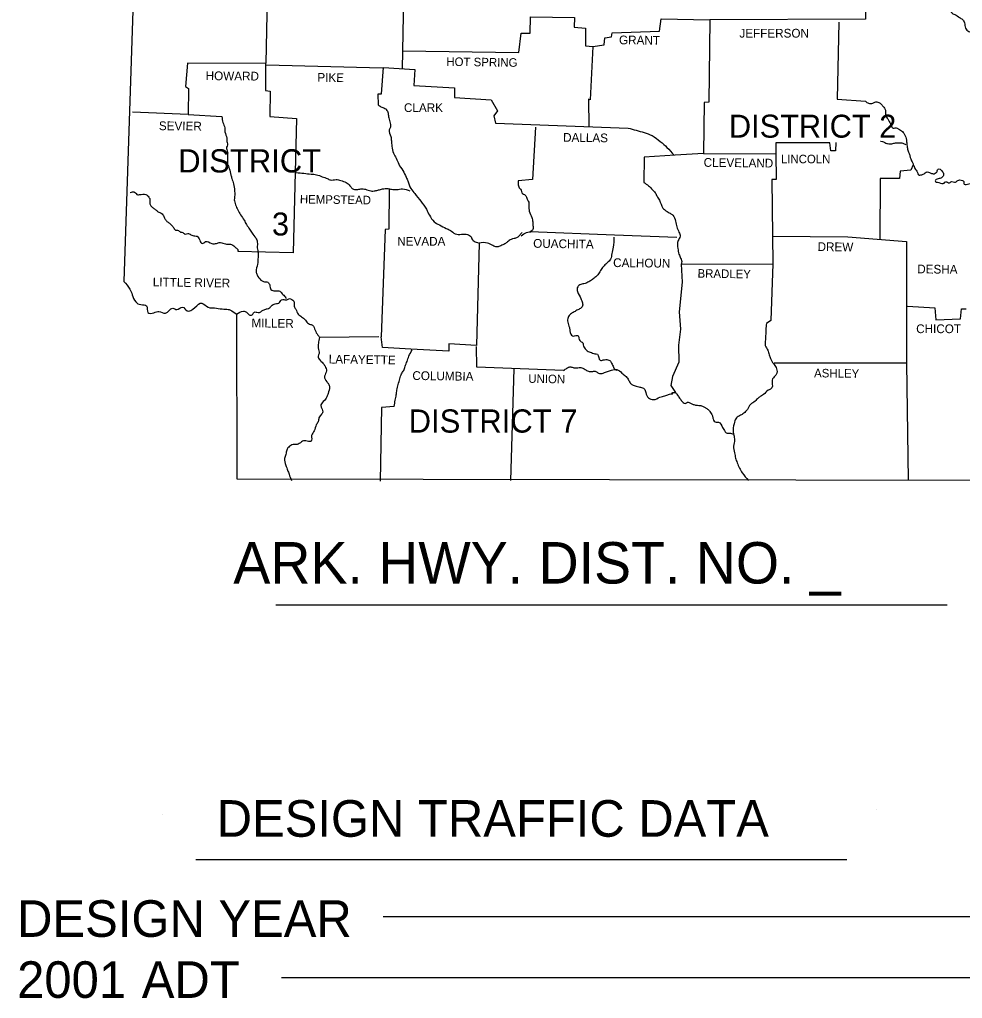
# Model space of a CAD drawing. Extents: x 76 to 6945, y -3933 to 2152.
# Drawn here: x 4972.5 to 5436, y -2483.3 to -2002.1 of the extents above; entities that cross this region are included whole.
import ezdxf

# ---------------------------------------------------------------- set-up
doc = ezdxf.new("R2010")
doc.units = 0
doc.layers.add('R_Draft', color=7, linetype='Continuous')

msp = doc.modelspace()

# ---------------------------------------------------------------- linework, layer by layer
at = {"layer": 'R_Draft'}
for p, q in [((5161.79, -1963.41), (5160.63, -2026.21)), ((5098.49, -2289.78), (5428.55, -2289.78)), ((5393.61, -2390.6), (5393.61, -2390.6)), ((5042.81, -2392.7), (5042.81, -2392.7)), ((5059.21, -2414.9), (5379.21, -2414.9)), ((5151.31, -2443.02), (5469.42, -2443.02)), ((5101.31, -2473.02), (5466.56, -2473.02))]:
    msp.add_line(p, q, dxfattribs=at)
for points in [[(5012.09, -1693.31), (5032.79, -1859.51), (5023.79, -2130.81)], [(5094.58, -1975.18), (5093.5, -2023.41)], [(5426.39, -1990.51), (5388.59, -1989.51), (5388.39, -2001.81), (5311.89, -2002.11)], [(5160.79, -2017.41), (5217.99, -2018.21), (5219.09, -2008.71), (5223.59, -2008.71), (5223.69, -2000.71), (5245.29, -2001.01), (5245.09, -2005.81), (5250.69, -2006.21), (5250.69, -2015.01), (5254.29, -2015.31), (5254.25, -2016.22)], [(5254.29, -2015.31), (5259.89, -2014.51), (5260.29, -2011.11), (5263.59, -2010.51), (5263.79, -2008.51), (5287.09, -2007.81), (5287.99, -2001.71), (5311.89, -2002.11)], [(5311.89, -2002.11), (5311.29, -2042.71), (5308.99, -2042.81), (5308.69, -2067.91)], [(5375.29, -2003.41), (5374.49, -2041.11), (5388.39, -2042.21)], [(5254.29, -2015.31), (5253.09, -2041.51), (5252.19, -2041.21), (5252.29, -2054.81)], [(5093.39, -2023.61), (5054.99, -2023.51), (5054.09, -2034.91), (5055.49, -2035.91), (5055.39, -2048.71), (5028.09, -2047.51)], [(5093.49, -2023.61), (5093.49, -2036.91), (5095.69, -2037.31), (5095.49, -2049.71), (5108.69, -2050.71), (5107.09, -2116.81), (5079.89, -2116.11)], [(5093.69, -2024.31), (5150.89, -2025.81)], [(5148.99, -2044.11), (5148.79, -2038.61), (5150.39, -2038.51), (5151.39, -2025.61), (5166.79, -2026.61), (5166.39, -2034.51), (5186.29, -2035.61), (5186.39, -2040.41), (5204.39, -2041.51), (5207.49, -2046.91), (5205.59, -2049.31), (5206.49, -2053.01), (5271.69, -2055.41)], [(5055.39, -2048.71), (5071.99, -2049.71)], [(5226.09, -2054.91), (5224.59, -2080.61), (5217.69, -2081.41)], [(5373.76, -2062.44), (5373.59, -2066.51), (5371.29, -2066.51), (5370.89, -2062.61), (5344.29, -2062.61), (5344.32, -2068.11)], [(5294.86, -2068.76), (5279.49, -2069.71), (5279.39, -2082.21)], [(5308.69, -2067.91), (5294.86, -2068.76)], [(5308.69, -2067.91), (5344.09, -2068.11)], [(5344.32, -2068.11), (5344.39, -2080.61), (5342.29, -2080.71), (5342.89, -2122.21)], [(5411.89, -2073.41), (5410.69, -2076.11), (5405.39, -2076.61), (5405.09, -2080.21), (5395.59, -2080.21), (5395.49, -2110.11)], [(5154.29, -2085.21), (5154.09, -2105.11), (5152.29, -2105.31), (5150.29, -2158.01)], [(5223.59, -2106.31), (5264.99, -2107.81), (5295.69, -2109.01)], [(5198.39, -2111.91), (5197.09, -2162.31), (5183.59, -2161.41), (5183.49, -2165.11), (5164.82, -2164.01)], [(5342.59, -2108.61), (5379.69, -2108.91), (5408.49, -2111.11)], [(5408.49, -2111.11), (5408.49, -2170.91), (5409.29, -2228.41)], [(5297.69, -2122.31), (5298.26, -2131.21), (5296.79, -2145.69), (5297.42, -2154.29), (5296.37, -2162.06), (5296.58, -2170.45), (5293.44, -2177.59), (5292.6, -2181.99), (5294.9, -2185.35)], [(5297.69, -2122.31), (5342.89, -2122.21)], [(5342.89, -2122.21), (5341.89, -2150.01), (5339.69, -2151.41)], [(5408.99, -2143.01), (5422.39, -2143.81), (5422.99, -2149.61), (5435.09, -2149.21), (5435.59, -2144.31), (5437.89, -2144.31)], [(5079.09, -2146.91), (5079.29, -2227.81), (5445.79, -2228.41)], [(5149.18, -2158.02), (5119.99, -2158.31)], [(5164.82, -2164.01), (5150.99, -2163.21), (5150.29, -2158.01)], [(5239.99, -2174.51), (5197.29, -2172.91), (5197.09, -2162.81)], [(5215.49, -2173.81), (5213.89, -2228.71)], [(5343.49, -2170.81), (5408.49, -2170.81)], [(5156.69, -2192.31), (5150.49, -2192.71), (5149.79, -2229.01)]]:
    msp.add_lwpolyline(points, dxfattribs=at)
for points in [[(5426.39, -1990.51), (5426.69, -1994.61), (5429.09, -1995.21), (5430.09, -1996.31), (5430.59, -1998.61), (5432.29, -1999.61), (5434.59, -2001.01), (5435.99, -2002.01), (5436.99, -2003.61), (5437.59, -2006.21), (5439.19, -2007.91), (5441.39, -2008.71), (5442.99, -2010.61), (5443.99, -2013.31), (5445.59, -2014.51), (5447.19, -2016.61), (5447.99, -2017.51), (5449.39, -2019.91), (5450.79, -2021.11), (5451.79, -2021.81), (5453.39, -2022.31), (5455.39, -2023.61), (5456.69, -2025.61), (5456.69, -2027.11), (5456.19, -2029.41), (5455.79, -2031.81), (5455.59, -2034.51), (5455.39, -2036.91), (5456.29, -2038.91), (5455.79, -2041.91), (5454.79, -2043.51), (5454.69, -2045.71), (5454.39, -2049.01), (5453.99, -2050.91), (5453.09, -2054.01), (5451.79, -2055.61)], [(5148.99, -2044.11), (5150.59, -2045.11), (5152.49, -2046.01), (5153.49, -2047.51), (5153.89, -2049.81), (5154.59, -2052.31), (5154.79, -2054.91), (5154.19, -2056.31), (5154.99, -2059.51), (5155.29, -2061.71), (5155.59, -2064.31), (5156.39, -2067.81), (5157.69, -2070.21), (5158.89, -2073.11), (5160.89, -2076.21), (5162.59, -2079.61), (5163.39, -2081.41), (5164.89, -2085.11), (5166.79, -2087.61), (5169.79, -2091.41), (5172.49, -2095.31), (5173.99, -2098.21), (5176.29, -2101.41), (5178.89, -2103.01), (5182.19, -2104.71), (5184.29, -2105.71), (5186.69, -2107.41), (5189.79, -2107.61), (5192.09, -2107.61), (5194.19, -2108.51), (5195.19, -2110.31), (5196.99, -2111.51), (5198.39, -2111.91)], [(5388.39, -2042.21), (5389.89, -2043.21), (5391.99, -2043.11), (5393.39, -2042.51), (5394.49, -2042.61), (5395.99, -2043.51), (5396.99, -2044.71), (5397.69, -2045.61), (5398.19, -2047.01), (5398.19, -2048.31), (5398.69, -2050.11), (5399.29, -2050.81), (5400.09, -2052.11), (5400.59, -2053.31), (5400.89, -2054.11), (5401.99, -2055.41), (5402.99, -2055.31), (5403.89, -2055.41), (5405.09, -2056.11), (5406.89, -2057.51), (5407.19, -2057.91), (5408.39, -2060.51), (5408.59, -2062.11), (5408.79, -2064.21), (5409.19, -2066.21), (5409.99, -2068.41), (5410.39, -2069.91), (5411.29, -2072.01), (5411.89, -2073.41), (5412.69, -2075.21), (5413.89, -2077.21), (5414.39, -2078.41), (5416.09, -2078.31), (5417.29, -2077.81), (5418.19, -2077.01), (5419.29, -2077.11), (5420.49, -2077.51), (5422.09, -2077.81), (5423.09, -2077.21), (5423.59, -2076.81), (5423.69, -2075.91), (5424.59, -2075.41), (5425.59, -2076.11), (5426.69, -2077.71), (5426.69, -2078.71), (5426.29, -2079.31), (5424.99, -2080.11), (5423.19, -2080.71), (5422.69, -2081.41), (5424.39, -2082.21), (5427.09, -2082.41), (5427.79, -2081.81), (5429.59, -2082.31), (5430.29, -2081.81), (5432.69, -2081.91), (5433.79, -2081.11), (5435.99, -2081.21), (5436.69, -2081.71), (5436.69, -2082.61), (5438.49, -2083.01), (5439.79, -2082.71), (5441.49, -2083.21), (5442.99, -2084.01), (5443.79, -2085.11), (5444.79, -2086.31), (5445.69, -2086.01), (5446.39, -2085.11), (5447.89, -2083.51), (5447.89, -2082.51), (5448.29, -2081.81), (5448.79, -2080.81)], [(5071.99, -2049.71), (5072.49, -2052.71), (5073.39, -2055.31), (5073.49, -2057.31), (5074.39, -2060.31), (5074.39, -2061.41), (5074.69, -2063.61), (5074.29, -2064.81), (5074.79, -2067.21), (5074.69, -2069.01), (5074.69, -2070.51), (5074.79, -2073.01), (5075.59, -2075.21), (5076.39, -2078.51), (5076.89, -2080.21), (5077.69, -2082.81), (5078.19, -2086.01), (5078.29, -2088.41), (5078.09, -2090.61), (5078.69, -2093.11), (5079.79, -2095.61), (5081.19, -2098.01), (5082.89, -2100.71), (5084.09, -2102.81), (5085.59, -2105.11), (5086.79, -2107.01), (5088.59, -2109.41), (5089.39, -2111.41), (5089.39, -2114.21), (5089.79, -2116.81), (5089.69, -2119.71), (5089.49, -2122.31), (5088.79, -2125.91), (5089.29, -2127.61), (5091.19, -2130.11), (5092.39, -2130.81), (5094.49, -2131.21), (5095.49, -2132.61), (5096.09, -2134.71), (5098.19, -2135.41), (5100.49, -2135.61), (5101.59, -2136.81), (5103.09, -2138.41), (5103.59, -2139.21)], [(5271.69, -2055.41), (5279.49, -2057.61), (5283.49, -2059.11), (5287.49, -2062.01), (5290.79, -2064.91), (5294.09, -2068.61)], [(5395.8, -2061.9), (5395.99, -2061.91), (5397.29, -2062.21), (5398.39, -2062.81), (5399.19, -2063.01), (5400.39, -2063.21), (5401.39, -2063.11), (5403.09, -2062.71), (5404.09, -2062.71), (5405.69, -2062.71), (5406.69, -2062.81), (5408.19, -2063.61)], [(5108.49, -2077.31), (5112.29, -2077.61), (5115.79, -2078.01), (5118.49, -2078.31), (5121.29, -2079.31), (5123.79, -2080.21), (5125.39, -2080.91), (5128.09, -2080.71), (5130.39, -2081.21), (5132.99, -2082.11), (5134.89, -2083.81), (5136.09, -2085.11), (5138.39, -2085.61), (5140.29, -2085.31), (5142.59, -2085.51), (5145.19, -2086.31), (5147.29, -2086.21), (5148.99, -2085.81), (5150.99, -2085.31), (5153.49, -2085.11), (5155.39, -2085.51), (5157.89, -2085.61), (5160.79, -2085.31), (5164.39, -2086.31)], [(5217.69, -2081.41), (5217.69, -2083.31), (5218.39, -2085.11), (5219.09, -2085.91), (5219.39, -2087.21), (5220.29, -2087.81), (5221.59, -2089.01), (5222.29, -2090.71), (5222.79, -2091.81), (5222.79, -2093.21), (5222.89, -2094.61), (5223.09, -2096.31), (5224.29, -2099.31), (5224.59, -2100.51), (5224.79, -2101.51), (5224.89, -2103.21), (5224.89, -2105.21), (5223.59, -2106.31)], [(5279.39, -2082.21), (5281.69, -2083.71), (5283.59, -2085.71), (5284.99, -2087.21), (5285.89, -2088.91), (5287.09, -2090.91), (5288.79, -2094.71), (5290.29, -2096.01), (5292.39, -2097.31), (5293.69, -2098.21), (5294.99, -2101.11), (5295.59, -2104.01), (5296.69, -2106.61), (5297.19, -2108.61), (5296.29, -2110.61), (5296.09, -2114.61), (5296.69, -2117.31), (5297.49, -2119.31), (5297.99, -2121.61), (5297.69, -2122.31)], [(5026.89, -2087.01), (5029.09, -2086.91), (5030.59, -2088.21), (5031.49, -2088.11), (5033.09, -2087.91), (5034.59, -2088.01), (5035.69, -2088.91), (5036.59, -2090.51), (5036.49, -2092.01), (5036.59, -2092.61), (5037.29, -2093.91), (5038.49, -2094.91), (5039.79, -2095.91), (5040.99, -2096.71), (5042.99, -2098.01), (5043.19, -2098.41), (5043.99, -2100.01), (5044.99, -2101.31), (5046.19, -2102.11), (5047.49, -2103.51), (5048.09, -2104.11), (5049.09, -2105.51), (5050.19, -2105.61), (5051.69, -2106.51), (5052.79, -2106.81), (5053.99, -2107.61), (5055.19, -2107.21), (5056.69, -2107.81), (5058.69, -2108.41), (5059.79, -2108.61), (5061.09, -2110.51), (5062.39, -2112.11), (5063.99, -2111.21), (5066.99, -2112.11), (5068.89, -2112.21), (5070.59, -2111.71), (5071.89, -2111.81), (5074.29, -2112.41), (5075.79, -2112.41), (5077.39, -2113.01), (5078.89, -2114.21), (5079.89, -2115.51), (5079.89, -2116.11)], [(5219.49, -2106.81), (5218.39, -2108.11), (5217.09, -2109.21), (5215.59, -2109.71), (5214.19, -2110.11), (5212.39, -2111.31), (5210.99, -2112.31), (5209.09, -2113.21), (5207.29, -2113.81), (5205.09, -2113.11), (5203.89, -2112.41), (5202.59, -2111.91), (5198.39, -2111.91)], [(5219.09, -2108.41), (5221.69, -2106.71), (5224.59, -2106.31)], [(5264.59, -2109.01), (5264.39, -2114.01), (5263.69, -2117.11), (5262.99, -2119.91), (5261.49, -2121.51), (5259.89, -2123.11), (5258.39, -2124.91), (5257.09, -2127.11), (5255.79, -2128.51), (5254.09, -2129.91), (5252.39, -2130.91), (5250.49, -2131.81), (5248.39, -2132.31), (5246.89, -2133.41), (5246.79, -2135.81), (5248.49, -2139.21), (5249.09, -2140.81), (5249.29, -2142.71), (5248.59, -2143.81), (5246.99, -2144.71), (5245.09, -2145.81), (5243.39, -2146.81), (5242.19, -2148.51), (5241.99, -2150.81), (5242.79, -2153.51), (5243.09, -2155.11), (5244.39, -2157.61), (5245.39, -2157.51), (5247.19, -2157.61), (5247.39, -2158.11), (5247.49, -2158.61), (5247.89, -2159.91), (5249.39, -2161.01), (5249.59, -2162.01), (5250.49, -2163.91), (5251.99, -2165.21), (5253.09, -2165.61), (5255.39, -2166.31), (5256.59, -2166.61), (5257.89, -2169.51), (5259.49, -2169.41), (5260.69, -2169.21), (5262.69, -2169.71), (5263.59, -2170.91), (5264.49, -2172.91), (5265.69, -2174.31), (5266.49, -2174.31)], [(5023.79, -2130.81), (5026.69, -2134.61), (5027.89, -2137.31), (5029.59, -2140.81), (5032.09, -2142.21), (5034.99, -2142.71), (5035.59, -2146.11), (5038.59, -2146.21), (5040.99, -2145.51), (5044.29, -2146.41), (5047.79, -2144.01), (5049.79, -2144.61), (5052.69, -2143.41), (5054.89, -2145.21), (5058.69, -2143.61), (5062.09, -2141.41), (5065.29, -2143.51), (5068.39, -2143.81), (5072.09, -2144.31), (5074.99, -2144.51), (5077.59, -2145.81), (5079.49, -2147.11), (5079.09, -2146.91)], [(5079.09, -2146.91), (5082.59, -2145.41), (5084.09, -2145.91), (5085.39, -2147.21), (5086.89, -2147.21), (5087.69, -2146.01), (5089.19, -2145.91), (5090.39, -2146.01), (5091.69, -2145.21), (5092.79, -2144.71), (5094.29, -2144.21), (5095.39, -2143.81), (5096.39, -2142.71), (5098.19, -2141.81), (5100.29, -2141.11), (5100.89, -2140.11), (5101.89, -2139.71), (5103.89, -2139.81), (5105.19, -2139.21), (5106.29, -2139.71), (5107.29, -2140.41), (5107.49, -2143.01), (5108.29, -2144.41), (5109.49, -2146.91), (5111.19, -2148.21), (5112.79, -2149.51), (5113.39, -2150.31), (5115.09, -2151.81), (5116.59, -2152.31), (5117.29, -2153.41), (5118.39, -2156.01), (5119.99, -2158.31)], [(5339.69, -2151.41), (5339.39, -2154.51), (5339.29, -2157.41), (5339.09, -2160.21), (5339.09, -2162.31), (5340.29, -2164.61), (5340.99, -2166.81), (5341.69, -2168.71), (5343.09, -2171.21), (5344.39, -2173.11), (5344.79, -2175.81), (5343.99, -2177.21), (5342.49, -2179.31), (5342.39, -2183.11), (5340.59, -2184.31), (5338.29, -2186.31), (5336.99, -2187.21), (5335.59, -2188.11), (5334.09, -2189.71), (5331.89, -2191.21), (5330.29, -2193.71), (5328.49, -2195.61), (5326.99, -2196.61), (5324.89, -2197.91), (5323.99, -2199.91), (5323.29, -2203.61), (5323.59, -2206.31), (5323.99, -2208.71), (5323.49, -2211.71), (5323.99, -2215.01), (5324.49, -2217.61), (5325.29, -2219.91), (5326.39, -2222.51), (5327.79, -2224.91), (5330.79, -2228.61)], [(5119.99, -2158.31), (5119.39, -2161.21), (5119.29, -2163.51), (5119.79, -2166.21), (5119.29, -2167.51), (5120.09, -2169.41), (5121.59, -2170.91), (5122.69, -2172.51), (5123.39, -2174.81), (5122.49, -2177.41), (5123.49, -2180.11), (5124.39, -2181.11), (5124.89, -2182.71), (5124.19, -2185.81), (5123.29, -2188.11), (5121.29, -2190.41), (5120.69, -2191.51), (5120.99, -2193.01), (5121.49, -2195.41), (5120.99, -2196.11), (5119.69, -2197.81), (5119.29, -2199.71), (5118.39, -2201.31), (5117.39, -2204.21), (5116.09, -2206.61), (5115.89, -2209.31), (5113.89, -2209.31), (5111.59, -2209.31), (5109.49, -2210.81), (5107.59, -2210.91), (5105.29, -2211.81), (5103.89, -2213.71), (5103.39, -2215.81), (5102.79, -2217.81), (5103.39, -2221.21), (5104.29, -2223.61), (5104.99, -2225.51), (5106.19, -2228.61)], [(5156.69, -2192.31), (5157.19, -2189.11), (5157.69, -2186.61), (5157.99, -2184.21), (5158.59, -2181.51), (5159.49, -2178.61), (5160.29, -2176.21), (5161.39, -2174.51), (5162.09, -2172.51), (5162.99, -2170.11), (5163.89, -2167.61), (5165.49, -2164.41)], [(5239.99, -2174.51), (5241.59, -2173.41), (5243.09, -2172.81), (5244.59, -2173.11), (5246.19, -2173.31), (5247.59, -2173.11), (5249.39, -2173.41), (5250.89, -2174.31), (5252.59, -2175.01), (5254.29, -2175.01), (5255.79, -2175.01), (5257.09, -2175.91), (5259.49, -2175.81), (5261.49, -2175.01), (5263.49, -2174.41), (5266.19, -2174.11), (5268.59, -2175.81), (5270.29, -2177.21), (5271.69, -2178.81), (5272.69, -2180.61), (5273.79, -2181.61), (5275.59, -2182.31), (5276.99, -2182.61), (5278.69, -2183.11), (5279.59, -2183.51), (5280.39, -2185.41), (5281.69, -2188.01), (5284.19, -2188.91), (5287.29, -2187.71), (5289.79, -2187.01), (5291.59, -2186.41), (5292.69, -2186.01), (5293.69, -2185.91), (5293.39, -2185.71), (5294.59, -2185.41), (5295.69, -2186.21), (5296.39, -2187.31), (5297.59, -2188.91), (5298.69, -2190.31), (5299.79, -2190.81), (5300.89, -2190.21), (5302.39, -2190.71), (5303.69, -2191.21), (5305.19, -2191.61), (5306.49, -2191.71), (5308.19, -2192.11), (5309.49, -2192.81), (5310.69, -2193.51), (5311.89, -2194.81), (5313.09, -2196.81), (5313.49, -2198.41), (5314.89, -2200.01), (5316.19, -2200.01), (5318.09, -2202.61), (5318.79, -2203.61), (5320.29, -2205.41), (5321.39, -2205.41), (5323.49, -2205.81)]]:
    msp.add_spline(points, degree=3, dxfattribs=at)

# ---------------------------------------------------------------- texts
for s, height, p in [('JEFFERSON', 4.3, (5326.39, -2010.91)), ('CLARK', 4.3, (5161.49, -2047.51)), ('DISTRICT 2', 11.3, (5321.23, -2060.12)), ('DISTRICT', 11.4, (5050.49, -2077.21)), ('LINCOLN', 4.2, (5346.79, -2072.71)), ('3', 11.3, (5096.59, -2108.21)), ('NEVADA', 4.3, (5158.19, -2113.21)), ('CHICOT', 4.3, (5413.29, -2156.21)), ('DISTRICT 7', 11.4, (5163.79, -2205.11)), ('  ARK. HWY. DIST. NO. _', 20.4, (5062.45, -2279.33)), ('DESIGN TRAFFIC DATA', 18, (5069.41, -2403.8)), ('DESIGN YEAR', 18, (4971.31, -2453.02)), ('2001', 18, (4971.31, -2483.02)), (' ADT', 18, (5025.91, -2483.02))]:
    msp.add_text(s, height=height, dxfattribs=at).set_placement(p)
for s, height, rotation, p in [('GRANT', 4.301, 359.4032, (5267.19, -2014.21)), ('HOT SPRING', 4.201, 359.2216, (5182.29, -2024.81)), ('HOWARD', 4.301, 359.5145, (5063.99, -2031.81)), ('PIKE', 4.299, 359.0452, (5118.89, -2032.61)), ('SEVIER', 4.301, 359.4271, (5040.99, -2056.41)), ('DALLAS', 4.3, 359.2462, (5239.69, -2062.11)), ('CLEVELAND', 4.301, 359.3376, (5308.79, -2074.41)), ('HEMPSTEAD', 4.199, 359.1885, (5110.29, -2092.41)), ('OUACHITA', 4.301, 359.2043, (5224.99, -2114.21)), ('DREW', 4.299, 359.2258, (5364.79, -2115.81)), ('CALHOUN', 4.301, 359.3634, (5264.29, -2123.71)), ('BRADLEY', 4.199, 359.1449, (5305.79, -2128.91)), ('DESHA', 4.299, 359.3704, (5413.79, -2126.81)), ('LITTLE RIVER', 4.3007, 359.1697, (5037.99, -2133.21)), ('MILLER', 4.3, 359.1319, (5086.49, -2153.31)), ('LAFAYETTE', 4.299, 359.1839, (5124.49, -2171.11)), ('COLUMBIA', 4.3, 359.2125, (5165.59, -2179.21)), ('ASHLEY', 4.201, 359.2361, (5363.09, -2177.91)), ('UNION', 4.201, 358.9584, (5222.59, -2180.61))]:
    msp.add_text(s, height=height, rotation=rotation, dxfattribs=at).set_placement(p)

doc.saveas('drawing.dxf')
